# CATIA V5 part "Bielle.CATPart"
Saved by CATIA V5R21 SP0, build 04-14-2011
Part number: bielle
Nomenclature: EP-01
Material "Laiton": density 8216 kg/m3, Young's modulus 1.31e+11 Pa, Poisson ratio 0.35, thermal expansion 1.67e-05 1/K
Bounding box of the stored display mesh (mm): x -4.5 to 4.5, y -3.5 to 3.5, z -20.75 to 20.75
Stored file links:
  C:\Users\Olivier\Desktop\redaction CATIA (local)\CATIA\DONNEES\Exercice mise en plan 1 (bielle)\bielle.CATPart
  C:\Program Files\Dassault Systemes\B21\win_b64\startup\materials\French\Catalog.CATMaterial
  C:\Users\Olivier\Desktop\redaction CATIA (local)\pompe à moteur de ventilation refait\Pompe_a_moteur_de_ventilation.CATProduct
  C:\Users\Olivier\Desktop\redaction CATIA (local)\pompe à moteur de ventilation refait\Ecrou a collerette M5.CATPart
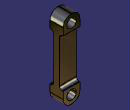
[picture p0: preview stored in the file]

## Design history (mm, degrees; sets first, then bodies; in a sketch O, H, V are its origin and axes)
Body1 (main body), material "Laiton"
  Sketch1 on yz-plane, origin (0, 0, 0), H (0, 1, 0), V (0, 0, 1)
    line L1 (3.5, 20.75) -> (3.5, 12.75)
    line L2 (3.5, -20.75) -> (-3.5, -20.75)
    line L3 (-3.5, -20.75) -> (-3.5, -12.75)
    line L4 (-3.5, 20.75) -> (3.5, 20.75)
    point P1 (3.5, 20.75)
    point P2 (3.5, -20.75)
    point P5 (3.5, 12.75)
    point P6 (-3.5, 12.75)
    point P7 (-3.5, -12.75)
    point P8 (3.5, -12.75)
    line L5 (1.5, 12.75) -> (1.5, -12.75)
    point P9 (1.5, 12.75)
    point P10 (1.5, -12.75)
    point P11 (-1.5, -12.75)
    point P12 (-1.5, 12.75)
    line L6 (-1.5, 12.75) -> (-1.5, -12.75)
    line L7 (3.5, -12.75) -> (3.5, -20.75)
    line L8 (-3.5, 12.75) -> (-3.5, 20.75)
    point P13 (1.5, 12.75)
    point P14 (-1.5, 12.75)
    point P15 (-1.5, -12.75)
    point P16 (1.5, -12.75)
    line L9 (3.5, 12.75) -> (1.5, 12.75)
    point P17 (1.5, 12.75)
    line L10 (-3.5, 12.75) -> (-1.5, 12.75)
    point P18 (-1.5, 12.75)
    line L11 (-3.5, -12.75) -> (-1.5, -12.75)
    point P19 (-1.5, -12.75)
    line L12 (3.5, -12.75) -> (1.5, -12.75)
    point P20 (1.5, -12.75)
    length L4 = 7
    distance L5 V = 1.5
    distance P1 P2 = 41.5
    length L1 = 8
    length L3 = 8
    vertical: L1 V, L3 V, L5 V, L7 V, L8 V
    horizontal: L2 H, L4 H, L9 H, L10 H, L11 H, L12 H
    equidistance: L1 L3 O, L2 L4 O
    coincidence: P6 L3, L1 L7, L3 L8, L5 P9, L6 P12, L6 P11, L5 P10, P14 P12, P13 P9, P17 L5, P18 L6, P12 P18, P11 P15, P16 P10, P19 L6, P20 L5, P11 P19
    symmetry: P6 P7 H, P5 P8 H, P10 P11 V, P9 P12 V, L5 L6 V
  Pad1: profile Sketch1, direction (1, 0, 0), length 4.5, mirrored extent
  Sketch2 on zx-plane, origin (0, 0, 0), H (-1, 0, 0), V (0, 0, 1)
    circle A1 centre (0, 16.5) radius 2.5
    point P1 (0, 16.5)
    circle A2 centre (0, -16.5) radius 2.5
    distance P1 H = 16.5
    coincidence: P1 V
    symmetry: A1 A2 H
  Pocket1: profile Sketch2, direction (0, -1, 0), length 4.5, mirrored extent
  Fillet1: radius 4.25, on edge [start face of Pad1 | face of Pad1 from Sketch1.L2]; edge [face of Pad1 from Sketch1.L2 | end face of Pad1]; edge [start face of Pad1 | face of Pad1 from Sketch1.L4]; edge [face of Pad1 from Sketch1.L4 | end face of Pad1]
  Fillet2: radius 1.5, on edge [face of Pad1 from Sketch1.L9 | face of Pad1 from Sketch1.L5]; edge [face of Pad1 from Sketch1.L5 | face of Pad1 from Sketch1.L12]; edge [face of Pad1 from Sketch1.L11 | face of Pad1 from Sketch1.L6]; edge [face of Pad1 from Sketch1.L6 | face of Pad1 from Sketch1.L10]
